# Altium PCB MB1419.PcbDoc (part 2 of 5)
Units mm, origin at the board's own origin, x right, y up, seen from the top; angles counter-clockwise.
Board outline 31 x 41 mm, 8 copper layers (Top Layer, Signal Layer 1, Signal Layer 2, Signal Layer 3, Signal Layer 4, Signal Layer 5, Signal Layer 6, Bottom Layer), stack 1.536 mm thick; 212 components, 125 nets, 637 pads, 2405 vias.
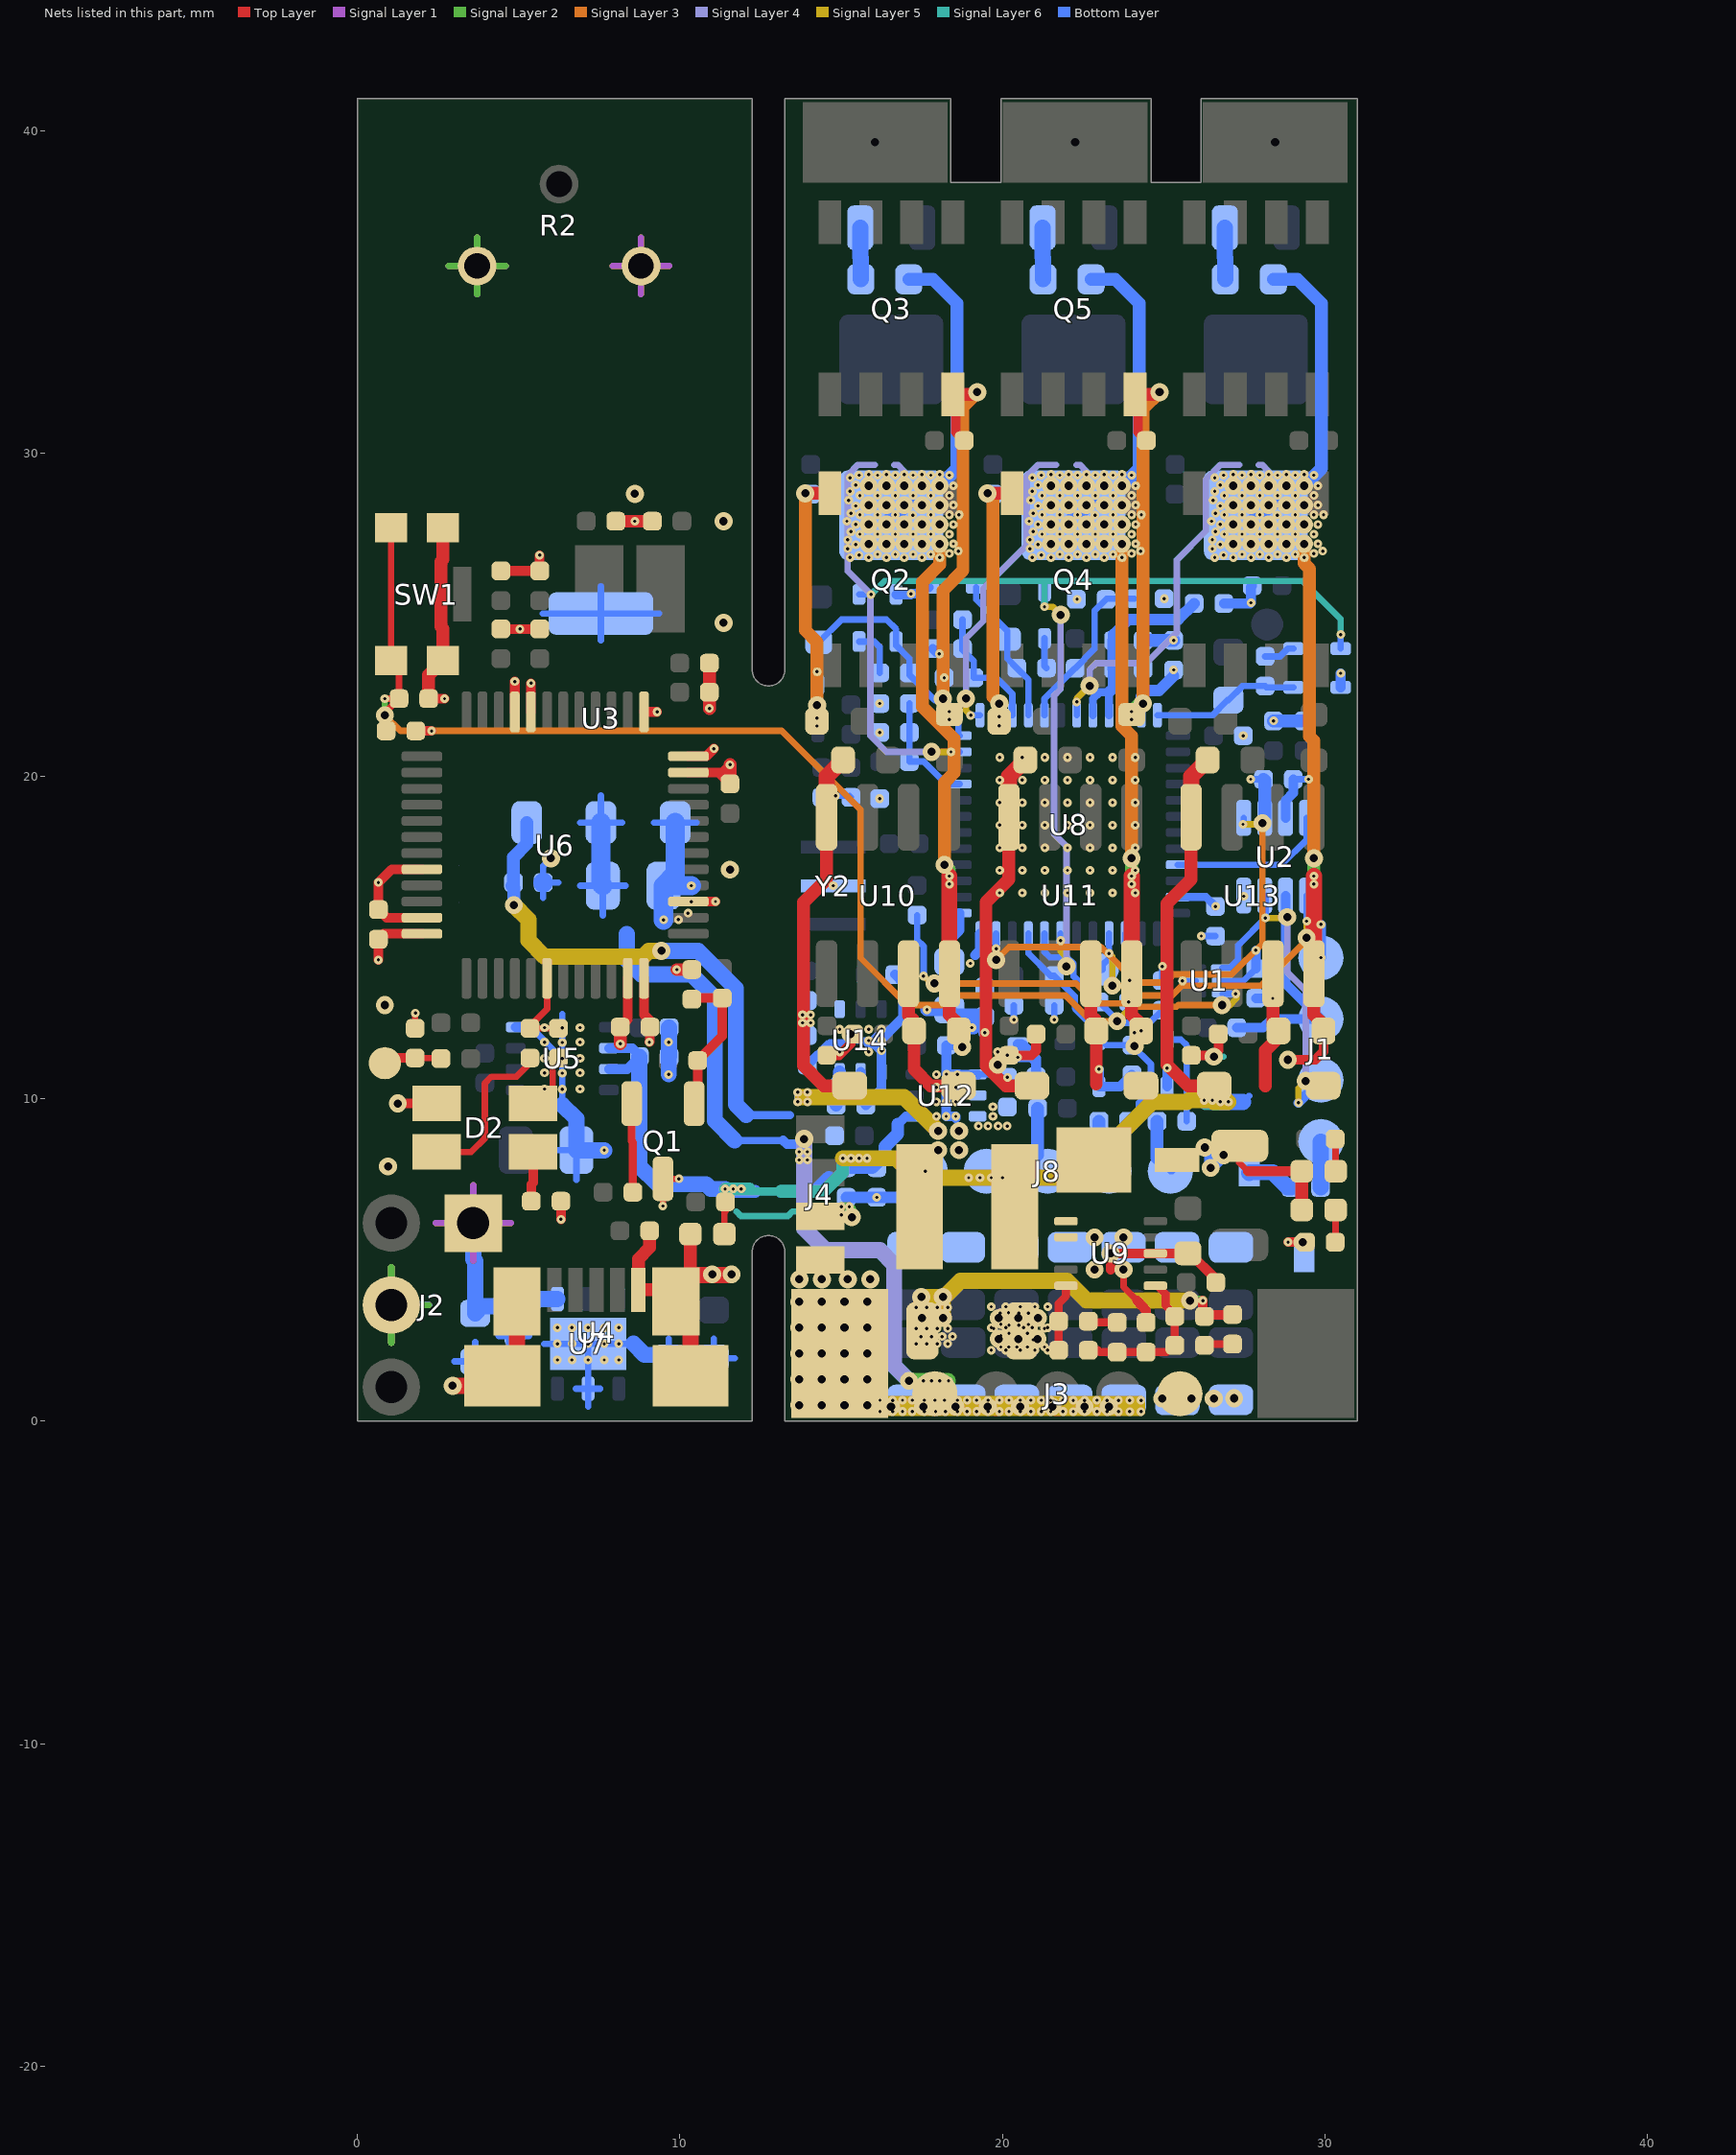
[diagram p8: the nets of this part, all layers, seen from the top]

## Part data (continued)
R64 R65 R66: library part RES, "RES SMD 22K OHM 1% 1/10W 0402", Manufacturer="Panasonic Electronic Components", Manufacturer PN=ERJ-2RKF2202X, Package Size="0402 (1005 Metric)", Rated Power="0.1W, 1/10W", Temperature Coefficient=100ppm/C, Tolerance=1%
R68: library part RES, "RES SMD 169K OHM 1% 1/16W 0402", Manufacturer=Yageo, Manufacturer PN=RC0402FR-07169KL, Package Size="0402 (1005 Metric)", Rated Power="0.063W, 1/16W", Temperature Coefficient=100ppm/C, Tolerance=1%
R74 R75 R77: library part RES, "RES SMD 1.8K OHM 1% 1/16W 0402", Manufacturer=Yageo, Manufacturer PN=RC0402FR-071K8L, Package Size="0402 (1005 Metric)", Rated Power="0.063W, 1/16W", Temperature Coefficient=100ppm/C, Tolerance=1%
R76: library part RES, "RES SMD 18K OHM 1% 1/16W 0402", Manufacturer=Yageo, Manufacturer PN=RC0402FR-0718KL, Package Size="0402 (1005 Metric)", Rated Power="0.063W, 1/16W", Temperature Coefficient=100ppm/C, Tolerance=1%
RT1: library part NTC, "NTC THERMISTOR 10K OHM 1% 0402", Manufacturer="TDK Corporation", Manufacturer PN=NTCG103JF103FT1, Package Size="0402 (1005 Metric)"
SW1: library part PUSHBUTTON-SPST-2, "SWITCH TACTILE SPST-NO 0.05A 32V", Manufacturer=C&K, Manufacturer PN=KMR211GLFS, Package Size="4.60mm x 2.80mm"
TP1 TP2 TP3: library part TESTPOINT, "TEST POINT 1MM  SMD PADSTASCK"
U1: library part AS11P2TLR, "IC ANLG SWITCH SGL SPDT 6QFN", Manufacturer=STMicroelectronics, Package Size=6-UFDFN
U2: library part TCAN330, "IC TXRX CAN 3.3V SOT-23", Manufacturer="Texas Instruments", Package Size=SOT-23-8, Supply Voltage="3 V ~ 3.6 V"
U3: library part LD1117SxxxTR_0, "IC REG LINEAR 5V 800MA SOT223", Manufacturer=STMicroelectronics, Package Size="TO-261-4, TO-261AA"
U4: library part USB_MICRO, "CONN RCPT 5POS MICRO USB R/A", Manufacturer="Molex, LLC", Manufacturer PN=0473460001
U5: "IC PWR SWITCH 1.2A HISIDE 8-DFN", Manufacturer=STMicroelectronics, Package Size="8-VDFN Exposed Pad", Supply Voltage="Not Required"
U6: "IC MCU 32BIT 128KB FLASH 48LQFP", Manufacturer=STMicroelectronics, Package Size=48-LQFP, Supply Voltage="2 V ~ 3.6 V"
U7: "IC REG LINEAR 3.3V 500MA 6DFN", Manufacturer=STMicroelectronics, Package Size="6-VDFN Exposed Pad"
U8: library part STM32_LQFP64_6
U9: "IC REG BUCK ADJ 3A 10VDFPN", Manufacturer=STMicroelectronics, Package Size="10-VFDFN Exposed Pad"
U10 U11 U13: library part L6387E, "IC DRIVER HI/LO SIDE HV 8-SOIC", Manufacturer=STMicroelectronics, Package Size="8-SOIC (0.154\", 3.90mm Width)", Supply Voltage="17V (Max)"
U12 U14: library part LDFPxR, "IC REG LINEAR POS ADJ 1A 6DFN", Manufacturer=STMicroelectronics, Package Size="6-VDFN Exposed Pad"
Y1: library part crystal, "CRYSTAL 8.0000MHZ 8PF SMD", Frequency Stability=150ppm, Frequency Tolerance=50ppm, Manufacturer="NDK America, Inc.", Package Size="0.126\" L x 0.098\" W (3.20mm x 2.50mm)"
Y2: library part resonator, "CER RES 8.0000MHZ 33PF SMD", Frequency Stability=0.13%, Frequency Tolerance=0.1%, Manufacturer="Murata Electronics North America", Manufacturer PN=CSTNE8M00GH5C000R0, Package Size="0.126\" L x 0.051\" W (3.20mm x 1.30mm)"

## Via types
v1: diameter 0.27, hole 0.1, Top Layer to Signal Layer 1, 715 vias
v2: diameter 0.27, hole 0.1, Signal Layer 6 to Bottom Layer, 503 vias
v3: diameter 0.27, hole 0.1, Signal Layer 1 to Signal Layer 2, 497 vias
v4: diameter 0.27, hole 0.1, Signal Layer 5 to Signal Layer 6, 309 vias
v5: diameter 0.559, hole 0.254, Top Layer to Bottom Layer, 214 vias
v6: diameter 0.559, hole 0.254, Signal Layer 2 to Signal Layer 5, 155 vias
v7: diameter 0.254, hole 0.254, Top Layer to Bottom Layer, 12 vias

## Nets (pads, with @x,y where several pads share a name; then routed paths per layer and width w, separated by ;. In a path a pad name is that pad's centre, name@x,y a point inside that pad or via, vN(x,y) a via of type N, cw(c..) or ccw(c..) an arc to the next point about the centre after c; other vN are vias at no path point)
5V_ESC: C9.1 C57.1 C63.1 C70.1 D1.C J8.4 R42.2 U5.6 U5.7 U12.1 U14.5 U14.6 | length 37.7
  Signal Layer 5 w0.5: v4(15.05,8.15) v4(15.3,8.15) v4(15.55,8.15) v4(15.8,8.15) 16.7,8.15 17.3,7.55 v2(18.95,7.55) v2(19.3,7.55) v2(19.65,7.55) v2(20,7.55) 22.3,7.55 24.65,9.9 25.713,9.9 25.763,9.95 v4(26.25,9.95) v4(26.5,9.95) 26.55,9.9 v4(26.75,9.9) v4(27,9.9)
  Signal Layer 6 w0.2: 12.146,7.2 12.2,7.146
  Signal Layer 6 w0.25: 12.2,7.146 12.225,7.121 13.129,7.121
  Signal Layer 6 w0.4: v2(11.4,7.2) v2(11.65,7.2) v2(11.9,7.2) 12.146,7.2 ; 13.129,7.121 14.458,7.121 15.05,7.713 v4(15.05,8.15) v4(15.3,8.15) v4(15.55,8.15) v4(15.8,8.15)
  Signal Layer 6 w0.5: v4(26.25,9.95) 26.3,9.9 26.45,9.9 v4(26.5,9.95) 26.55,9.9 v4(26.75,9.9) v4(27,9.9)
  Bottom Layer w0.2: C9.1@8.74,11.3 C9.1@8.74,11.35 ; 27.45,9.9 27.631,10.081 D1.C@27.65,10.081
  Bottom Layer w0.25: 12.323,7.127 12.477,7.127 12.483,7.121 12.917,7.121 12.923,7.127 13.15,7.127
  Bottom Layer w0.3: U5.7@7.795,10.915 8.365,10.915 8.74,11.29 C9.1@8.74,11.3 ; U5.6@7.795,11.565 8.525,11.565 C9.1@8.74,11.35 ; U14.6@14.95,10.6 15.103,10.447 15.386,10.447 15.6,10.661 U14.5@15.6,10.825 ; 16.75,9.2 17,9.45 U12.1@17.275,9.45
  Bottom Layer w0.4: v2(11.4,7.2) 11.45,7.2 11.523,7.127 12.323,7.127 ; 13.15,7.127 14.177,7.127 14.61,7.56 ; C63.1@14.84,9.8 14.84,10.49 14.95,10.6 U14.6@14.95,10.825 ; C57.1@15.15,7.86 15.95,7.86 16.35,8.26 16.35,8.51 16.75,8.91 16.75,9.2
  Bottom Layer w0.5: C9.1@8.74,11.29 8.74,7.91 9.3,7.35 10.8,7.35 10.95,7.2 v2(11.4,7.2) ; v4(26.25,9.95) 26.7,9.95 v4(26.75,9.9) 27.45,9.9
  other v2: 15.05,8.15 15.3,8.15 15.55,8.15 15.8,8.15 26.75,9.9 26.25,9.95
  other v4: 18.95,7.55 19.3,7.55 19.65,7.55 20,7.55
+3.3V: C1.1 C2.1 C18.1 C19.2 C20.1 C24.1 C64.1 D10.C D12.C D14.C D16.C D17.C D18.C D19.C J4.3 L1.1 R29.1 R49.2 R64.2 R65.2 R66.2 R71.1 R72.1 R73.2 RT1.1 U1.2 U2.3 U8.1 U8.23 U8.35 U8.48 U14.1 | length 21.6
  Top Layer w0.2: J4.3@14.7,6.35 15,6.35 v3(15,6.4) v3(15,6.65)
  Top Layer w0.3: v3(28.85,5.55) R29.1@29.39,5.55
  Signal Layer 2 w0.2: v3(15,6.4) 15,6.45 15.15,6.6 15.2,6.6 v3(15.25,6.65) v6@15.25,6.45 ; v3(28.85,5.55) v6(29.3,5.55)
  Signal Layer 2 w0.27: v3(15,6.4) 15.075,6.325 v6(15.325,6.325) 15.325,6.575 v3(15.25,6.65) v3(15,6.65) v3@15,6.45
  Bottom Layer w0.2: v4(13.8,12.35) 13.95,12.2 C64.1@13.95,11.96 ; R71.1@24.95,13.66 v4(24.95,14.1) ; U1.2@26.82,13.65 27.47,13.65 C1.1@27.85,14.03 ; C2.1@29.01,19.9 v4(29.487,19.9)
  Bottom Layer w0.25: U8.23@24.3,21.885 24.3,22.465 ; C24.1@25.3,23.1 v4(25.3,23.29) ; U8.35@25.435,16.25 26.31,16.25 v4(26.6,15.96)
  Bottom Layer w0.3: v4(14.25,23.237) 14.27,23.217 D16.C@14.27,22.83 ; D10.C@16.7,25.63 17.143,25.63 v4(17.163,25.65) 17.35,25.65 17.55,25.85 D12.C@17.72,25.85 ; R65.2@17.84,23.95 17.94,23.85 17.98,23.85 v4(18.04,23.79) ; 18.45,15 18.665,15.215 U8.1@18.665,15.75 ; 19.15,14.45 19.3,14.6 U8.48@19.3,15.115 ; R73.2@21.04,10.68 21.04,11.13 ; v4(22.99,10.91) D18.C@22.99,10.37 23.64,10.37 R72.1@24.01,10.74 ; D17.C@25.1,10.37 v4(25.1,10.95) ; L1.1@26.86,25.35 27.677,25.35 v4(27.7,25.373) 27.7,25.86 RT1.1@27.74,25.9 ; C1.1@27.85,14.03 v4(27.85,14.6) ; U2.3@28.775,18.705 28.775,19.24 29.01,19.475 C2.1@29.01,19.9 ; D14.C@30.48,22.75 v4(30.48,23.187) ; D19.C@20.47,11.7 v4(20.47,11.28) 20.89,11.28 ; D19.C@20.47,11.7 20.89,11.28 ; D19.C@20.47,11.7 20.59,11.7 21.01,11.28 ; 20.89,11.28 21.01,11.28 ; 20.89,11.28 21.04,11.13 ; 21.01,11.28 21.04,11.25 21.04,11.13
  Bottom Layer w0.35: 24.3,22.465 24.485,22.65 24.85,22.65 C24.1@25.3,23.1
  other v1: 28.85,5.55 15,6.4 15,6.65 15.25,6.65
  other v2: 22.99,10.91 25.1,10.95 20.47,11.28 13.8,12.35 14.05,12.35 13.8,12.6 14.05,12.6 24.95,14.1 19,14.195 27.85,14.6 26.6,15.96 29.487,19.9 16.19,22.25 30.48,23.187 14.25,23.237 25.3,23.29 18.04,23.79 27.7,25.373 22.31,25.48 17.163,25.65
  other v4: 14.05,12.35 13.8,12.6 14.05,12.6 19,14.195 16.19,22.25 22.31,25.48
+3V3_ST_LINK: C3.1 C4.1 C16.1 C17.1 J2.1 Q1.3 R2.3 R10.1 R11.1 R15.1 R19.2 U6.1 U6.9 U6.24 U6.36 U6.39 U6.48 U7.4 | length 33.2
  Top Layer w0.2: v1(9.47,6.67) Q1.3@9.47,7.515 v1(9.965,7.515)
  Top Layer w0.3: v1(0.65,14.3) C3.1@0.65,14.94 0.82,15.11 U6.24@2,15.11 ; R10.1@1.81,21.4 v1(2.3,21.4) ; R19.2@4.45,26.36 R15.1@5.65,26.36 v3(5.65,26.85) ; U6.9@4.88,21.99 v1(4.88,22.93) ; v1(6.31,6.26) R11.1@6.31,6.82 ; U6.36@8.88,13.73 8.88,12.61 9.07,12.42 9.07,11.77 v1(9.05,11.75) ; U6.1@8.88,21.99 v1(9.29,21.99) ; U6.39@10.26,16.11 v1(11.1,16.11) ; U6.48@10.26,20.61 10.81,20.61 v1(11.05,20.85)
  Signal Layer 1 w0.2: 2.423,6.14 J2.1@3.59,6.14 ; 3.59,4.973 J2.1@3.59,6.14 ; 3.59,7.307 J2.1@3.59,6.14 ; 4.757,6.14 J2.1@3.59,6.14 ; 7.912,35.815 R2.3@8.79,35.815 ; 8.79,34.937 R2.3@8.79,35.815 ; 8.79,36.693 R2.3@8.79,35.815 ; 9.668,35.815 R2.3@8.79,35.815
  Signal Layer 5 w0.2: 2.423,6.14 J2.1@3.59,6.14 ; 3.59,4.973 J2.1@3.59,6.14 ; 3.59,7.307 J2.1@3.59,6.14 ; 4.757,6.14 J2.1@3.59,6.14 ; 7.912,35.815 R2.3@8.79,35.815 ; 8.79,34.937 R2.3@8.79,35.815 ; 8.79,36.693 R2.3@8.79,35.815 ; 9.668,35.815 R2.3@8.79,35.815
  Bottom Layer w0.5: J2.1@3.59,6.14 3.59,5.024 3.65,4.964 C16.1@3.65,3.345 3.865,3.56 C17.1@4.85,3.56 5.367,3.56 5.597,3.79 U7.4@6.2,3.79
  other v1: 5.65,26.85
+5V: C6.1 J3.1 U3.2 U3.4 | length 38.3
  Top Layer w0.2: J3.1@17.9,0.85 J3.1@18.05,0.85 ; J3.1@18.297,1.25 J3.1@18.323,1.25
  Signal Layer 2 w0.2: v6(17.1,1.25) 17.108,1.258 v3@17.442,1.258
  Signal Layer 2 w0.5: v6(17.1,1.25) v3(17.55,1.25) v3(17.8,1.25) v3(18.05,1.25) v3@18.297,1.25
  Signal Layer 4 w0.5: v6(13.85,8.75) 13.85,5.971 14.521,5.3 16.2,5.3 16.636,4.864 16.636,1.714 v6(17.1,1.25)
  Signal Layer 5 w0.2: v4(13.7,8.35) 13.825,8.225 v4(13.95,8.1) ; v4(13.7,8.35) 13.7,8.6 v6(13.85,8.75) ; v4(13.7,8.35) v4(13.7,8.1) v4(13.95,8.1) ; v4(13.7,8.35) v4(13.95,8.35) ; v6(13.85,8.75) 13.95,8.65 v4@13.95,8.4 ; v6(13.85,8.75) 13.85,8.5 v4@13.95,8.4 ; v4(13.95,8.1) v4(13.95,8.35) ; v4(13.95,8.35) v4@13.95,8.4
  Bottom Layer w0.2: 5.747,25.04 U3.4@7.55,25.04 ; 6.897,18.56 U3.2@7.55,18.56 ; 6.907,16.6 C6.1@7.61,16.6 ; 7.55,19.398 U3.2@7.55,18.56 ; 7.55,24.202 U3.4@7.55,25.04 ; 7.55,25.878 U3.4@7.55,25.04 ; 7.61,15.682 C6.1@7.61,16.6 ; 7.61,17.518 C6.1@7.61,16.6 ; 8.203,18.56 U3.2@7.55,18.56 ; 8.313,16.6 C6.1@7.61,16.6 ; 8.35,15.1 8.35,15.2 ; 9.353,25.04 U3.4@7.55,25.04 ; v4(13.7,8.35) v4(13.7,8.1) v4(13.95,8.1)
  Bottom Layer w0.22: 11.7,8.7 13.2,8.7
  Bottom Layer w0.3: 13.2,8.7 13.314,8.586 13.85,8.586
  Bottom Layer w0.5: 8.35,15.1 8.35,14.3 8.8,13.85 10.352,13.85 11.08,13.122 11.08,9.32 11.7,8.7
  Bottom Layer w0.6: U3.2@7.55,18.56 7.55,16.66 C6.1@7.61,16.6
  other v1: 17.55,1.25 17.8,1.25 18.05,1.25 18.325,1.25
  other v2: 13.7,8.1 13.95,8.1 13.7,8.35 13.95,8.35
  other v3: 18.325,1.25
+10V: C5.1 C42.2 C45.2 C49.1 C55.1 C56.1 C62.1 D6.A D8.A D9.A L2.2 R30.1 U3.3 U10.3 U11.3 U12.5 U12.6 U13.3 | length 48.6
  Top Layer w0.3: v3(26.21,3.74) 26.21,3.4 26.26,3.35 R30.1@26.26,3.25 26.31,3.3 27.12,3.3 C42.2@27.13,3.31
  Top Layer w0.4: U10.3@17.085,13.875 17.085,12.578 17.255,12.408 C49.1@17.255,12.1 17.255,10.918 17.773,10.4 D6.A@18.575,10.4 ; U11.3@22.735,13.875 22.735,12.578 22.905,12.408 C55.1@22.905,12.1 22.905,10.449 ; 28.15,10.4 28.15,11.5 28.555,11.905 C62.1@28.555,12.1 28.385,12.27 U13.3@28.385,13.875
  Signal Layer 2 w0.3: v6(25.81,3.74) v3(26.21,3.74)
  Signal Layer 3 w0.2: v6@18.085,3.87 18.1,3.856 v6(18.15,3.856)
  Signal Layer 5 w0.2: 14.1,10.05 v4(13.95,10.2) ; v4(13.65,10.2) v4(13.95,10.2) ; v4(13.65,10.2) v4(13.65,9.9) v4(13.95,9.9) ; v4(13.65,10.2) v4(13.95,9.9) ; v4(13.95,9.9) v4(13.95,10.2)
  Signal Layer 5 w0.5: v5(4.85,16) 5.3,15.55 5.3,14.9 5.8,14.4 8.85,14.4 9.031,14.581 v5(9.422,14.581) ; 14.1,10.05 16.95,10.05 v6(18,9) ; v6(25.81,3.74) 22.61,3.74 22,4.35 18.7,4.35 18.206,3.856 v6(18.15,3.856) ; v6(17.479,3.848) 17.811,3.516 v6@18.127,3.2 ; v6(17.479,3.848) 17.479,3.221 v6(17.5,3.2) v6@18.127,3.2 ; v6(17.479,3.848) 17.487,3.856 v6(18.15,3.856) ; v6@18.127,3.2 v6(18.15,3.2) v6(18.15,3.856)
  Bottom Layer w0.2: C5.1@4.79,16.6 4.79,16.65 C5.1@4.84,16.7 ; 12.05,9.5 12.057,9.493 ; 13.412,9.493 13.419,9.5 ; v4(13.65,9.9) 13.641,9.908 13.641,10.192 v4(13.65,10.2)
  Bottom Layer w0.25: 12.057,9.493 13.412,9.493
  Bottom Layer w0.4: v5(4.85,16) 4.85,16.54 4.79,16.6 4.84,16.65 C5.1@4.84,16.7 4.84,17.49 5.25,17.9 U3.3@5.25,18.56
  Bottom Layer w0.5: v5(9.422,14.581) 10.569,14.581 11.73,13.42 11.73,9.82 12.05,9.5
  other v1: 17.325,2.4 17.65,2.4 17.975,2.4 18.3,2.4 17.475,2.625 17.8,2.625 18.125,2.625 18.45,2.625 17.325,2.875 17.65,2.875 17.975,2.875 18.3,2.875 17.325,3.525 17.65,3.525 17.975,3.525 18.3,3.525 26.21,3.74
  other v2: 19.25,9.15 19.55,9.15 19.86,9.15 20.142,9.15 19.7,9.45 19.7,9.75 13.65,9.9 13.95,9.9 13.65,10.2 13.95,10.2
  other v3: 17.325,2.4 17.65,2.4 17.975,2.4 18.3,2.4 17.475,2.625 17.8,2.625 18.125,2.625 18.45,2.625 17.325,2.875 17.65,2.875 17.975,2.875 18.3,2.875 17.325,3.525 17.65,3.525 17.975,3.525 18.3,3.525
  other v4: 19.25,9.15 19.55,9.15 19.86,9.15 20.142,9.15 19.7,9.45 19.7,9.75
  other v6: 18,8.4 18.65,8.4 18.65,9
A+/H1: C67.1 D17.A R71.2 R74.2 U8.44 | length 9.5
  Bottom Layer w0.2: U8.44@21.3,15.115 21.3,14.55 21.47,14.38 22,14.38 22.2,14.18 22.2,13.79 23.64,12.35 24.56,12.35 R71.2@24.95,12.74 25.1,12.59 D17.A@25.1,11.83 25.527,11.83 25.71,11.647 R74.2@25.71,9.3
B+/H2: C68.1 D18.A R72.2 R75.2 U8.45 | length 8.2
  Bottom Layer w0.2: U8.45@20.8,15.115 20.8,14.5 21.49,13.81 C68.1@21.6,13.81 22.24,13.17 22.24,12.8 22.99,12.05 D18.A@22.99,11.83 23.05,11.83 23.22,11.66 R72.2@24.01,11.66 24.6,11.07 24.6,10.25 24.22,9.87 24.22,9.61 R75.2@23.91,9.3
BEMF1: D10.A R57.1 R61.2 U8.12 | length 7.1
  Bottom Layer w0.2: R61.2@14.3,24.145 15.005,24.85 16.4,24.85 16.7,24.55 D10.A@16.7,24.17 16.7,24.05 17.11,23.64 17.11,23.138 17.898,22.35 18.2,22.35 18.63,21.92 18.63,21.25 U8.12@18.665,21.25
BEMF2: D12.A R58.1 R62.2 U8.16 | length 4.6
  Bottom Layer w0.2: D12.A@19.18,25.85 19.18,25.47 20.15,24.5 R62.2@20.15,24.245 20.15,23.64 R58.1@20.44,23.35 20.8,22.99 U8.16@20.8,21.885
BEMF3: D14.A R59.1 R63.2 U8.24 | length 4.6
  Bottom Layer w0.2: U8.24@24.8,21.885 26.5,21.885 26.97,22.355 R63.2@27,22.355 27.435,22.79 R59.1@28.14,22.79 28.18,22.75 D14.A@29.02,22.75
BUTTON: C8.1 R10.2 SW1.3 SW1.4 U8.39 | length 40
  Top Layer w0.2: v3(0.85,22.4) C8.1@1.29,22.4 ; R10.2@0.89,21.4 0.89,22 C8.1@1.29,22.4 ; SW1.3@1.045,27.695 SW1.4@1.045,23.584 1.29,23.34 C8.1@1.29,22.4
  Signal Layer 2 w0.2: v6(0.85,21.884) v3(0.85,22.4)
  Signal Layer 3 w0.2: v6(0.85,21.884) 1.334,21.4 13.15,21.4 15.6,18.95 15.6,14.35 17.05,12.9 18.35,12.9 18.65,13.2 21.95,13.2 22.75,12.4 v6(23.55,12.4)
  Signal Layer 5 w0.2: v6(23.55,12.4) 23.941,12.792 v4(23.941,13.662)
  Bottom Layer w0.2: U8.39@23.8,15.115 23.8,14.403 23.941,14.262 v4(23.941,13.662)
  other v1: 0.85,22.4
  other v2: 23.941,13.662
CAN_RX: U2.4 U8.33 | length 5
  Bottom Layer w0.2: U8.33@25.435,17.25 28.65,17.25 29.425,18.025 U2.4@29.425,18.705
CAN_SHDN: TP2.1 U2.5 U8.40 | length 10.5
  Signal Layer 3 w0.2: v6(23.4,13.5) 23.75,13.5 24.05,13.2 25.25,13.2 25.55,13.5 28,13.5 29.425,14.925 v6(29.425,14.987)
  Signal Layer 5 w0.2: v4(23.3,14.5) 23.4,14.4 v6(23.4,13.5) ; v6(29.425,14.987) v4(29.425,15.503)
  Bottom Layer w0.2: TP2.1@23.1,14 23.1,14.15 23.3,14.35 v4(23.3,14.5) U8.40@23.3,15.115 ; v4(29.425,15.503) U2.5@29.425,16.295
  other v2: 23.3,14.5 29.425,15.503
CAN_TERM: R26.2 U1.3 | length 12.8
  Signal Layer 3 w0.2: v6(17.89,13.571) 22.279,13.571 22.9,12.95 23.8,12.95 23.85,12.9 23.855,12.9 23.905,12.85 25.395,12.85 25.445,12.9 v6(26.8,12.9) v6@26.82,12.9
  Signal Layer 5 w0.2: v4(17.55,13.8) 17.561,13.8 17.79,13.571 v6(17.89,13.571) ; v6(26.8,12.9) 27.05,12.9 27.25,13.1 v4@27.25,13.25
  Bottom Layer w0.2: R26.2@17.35,15.69 17.35,14.923 17.55,14.723 v4(17.55,13.8) ; U1.3@26.82,13.25 v2@27.25,13.25
  other v2: 27.225,13.25 17.55,13.8
  other v4: 27.225,13.25
CAN_TX: U2.1 U8.47 | length 14.7
  Signal Layer 3 w0.2: v6(19.8,14.3) 20.2,14.7 23.049,14.7 24.149,13.6 25.05,13.6 25.3,13.85 27.1,13.85 28.057,14.807 v6(28.057,18.539)
  Signal Layer 5 w0.2: v6(19.8,14.3) v4(19.8,14.65) ; v4(27.455,18.505) 28.023,18.505 v6(28.057,18.539)
  Bottom Layer w0.2: v4(19.8,14.65) U8.47@19.8,15.115 ; v4(27.455,18.505) 27.475,18.525 U2.1@27.475,18.705
  other v2: 19.8,14.65 27.455,18.505
CURR_FDBK1_OPAMP+: R64.1 R67.1 R80.2 U8.9 | length 3.6
  Bottom Layer w0.2: R64.1@17.11,22.25 R80.2@17.11,21.35 R67.1@17.11,20.45 17.55,20.45 18.25,19.75 U8.9@18.665,19.75
CURR_FDBK1_OPAMP-: JP1.1 U8.11 | length 12.3
  Signal Layer 4 w0.2: JP1.1@16.035,29.65 15.515,29.65 15.2,29.335 15.2,26.35 15.9,25.65 15.9,21.25 16.4,20.75 v6(17.8,20.75)
  Signal Layer 5 w0.2: v6(17.8,20.75) v4(18.4,20.75)
  Bottom Layer w0.2: v4(18.4,20.75) U8.11@18.665,20.75
  other v2: 18.4,20.75
CURR_FDBK2_OPAMP+: R65.1 R69.1 R81.2 U8.15 | length 4
  Bottom Layer w0.2: R69.1@18.76,24.85 R65.1@18.76,23.95 18.76,23.907 19.11,23.557 R81.2@19.11,23.05 19.795,23.05 20.3,22.545 U8.15@20.3,21.885
CURR_FDBK2_OPAMP-: JP2.1 U8.13 | length 9.6
  Signal Layer 4 w0.2: v6(18.865,22.401) 18.865,24.265 19.4,24.8 19.4,25.805 20.75,27.155 20.75,29.3 21.1,29.65 JP2.1@21.66,29.65
  Signal Layer 5 w0.2: v6(18.865,22.401) 18.865,22.035 v4(19.015,21.885)
  Bottom Layer w0.2: v4(19.015,21.885) U8.13@19.3,21.885
  other v2: 19.015,21.885
CURR_FDBK3_OPAMP+: R66.1 R70.1 R82.2 U8.17 | length 5.3
  Bottom Layer w0.2: U8.17@21.3,21.885 21.3,22.4 22.24,23.34 R70.1@22.25,23.34 22.85,23.94 22.85,25.12 R66.1@23.21,25.48 23.23,25.5 R82.2@24.09,25.5
CURR_FDBK3_OPAMP-: JP3.1 U8.19 | length 11.1
  Signal Layer 4 w0.2: v6(22.7,22.8) 22.7,23.3 22.9,23.5 24.45,23.5 25.4,24.45 25.4,26.7 26.3,27.6 26.3,29.2 26.75,29.65 JP3.1@27.34,29.65
  Signal Layer 5 w0.2: v4(22.3,22.3) 22.3,22.4 v6(22.7,22.8)
  Bottom Layer w0.2: U8.19@22.3,21.885 v4(22.3,22.3)
  other v2: 22.3,22.3
D: J1.2 U1.1 U2.7 | length 10.7
  Signal Layer 4 w0.2: v6(28.825,15.625) 28.825,13.925 29.4,13.35 v6(29.4,10.55)
  Signal Layer 5 w0.2: v4(28.15,15.6) 28.8,15.6 v6(28.825,15.625) ; v4(29.172,9.872) 29.172,10.322 v6(29.4,10.55)
  Bottom Layer w0.2: U1.1@26.805,14.05 27.04,14.05 27.3,14.31 27.3,14.75 v4(28.15,15.6) 28.15,16.295 U2.7@28.125,16.295
  Bottom Layer w0.3: v4(29.172,9.872) J1.2@29.87,10.57
  other v2: 29.172,9.872 28.15,15.6
GND: C1.2 C2.2 C3.2 C4.2 C5.2 C6.2 C7.2 C8.2 C9.2 C10.1 C11.1 C12.1 C13.2 C14.2 C15.2 C16.2 C17.2 C18.2 C19.1 C20.2 C21.2 C22.2 C23.2 C24.2 C25.2 C26.2 C27.1 C28.1 C29.1 C30.1 C31.1 C32.1 C33.1 C34.1 C35.1 C36.1 C37.1 C38.1 C39.1 C40.1 C41.2 C44.2 C45.1 C47.2 C48.2 C49.2 C51.2 C53.2 C54.2 C55.2 C56.2 C57.2 C59.2 C60.2 C61.2 C62.2 C63.2 C64.2 C65.2 C66.2 C67.2 C68.2 C69.2 C70.2 D2.C1 D3.C D4.C D5.C D7.A D20.A J1.4 J2.3 J3.5 J4.4 J6.1 J8.5 JP1.2 JP2.2 JP3.2 R2.1 R6.1 R7.1 R13.2 R14.2 R16.2 R17.2 R22.2 R32.2 R33.1 R46.2 R53.2 R54.2 R55.2 R56.2 R60.2 R76.2 R80.1 R81.1 R82.1 SW1.1 SW1.2 U1.5 U2.2 U2.8 U3.1 U4.5 U4.6 U4.7 U4.8 U4.9 U5.4 U5.9 U6.8 U6.20 U6.23 U6.35 U6.47 U7.2 U7.7 U8.49 U9.8 U9.11 U10.4 U11.4 U12.4 U12.7 U13.4 U14.4 U14.7 Y2.2 | length 257.3
  Top Layer w0.2: C12.1@1.79,12.18 1.79,12.64 v3(1.8,12.65) ; v5(23.75,4.7) 23.75,4.159 24.169,3.74 ; 26.21,11.34 26.25,11.3 v5(26.55,11.3) 26.69,11.44 v5@26.69,11.483 ; 27.333,8.017 27.6,7.75
  Top Layer w0.3: v5(1.25,9.85) D2.C1@2.45,9.85 ; U6.23@2,15.61 0.9,15.61 C3.2@0.65,15.86 v3(0.65,16.7) 1.06,17.11 U6.20@2,17.11 ; C8.2@2.21,22.4 v3(2.7,22.4) ; R22.2@4.45,24.56 v3(5.04,24.56) C13.2@5.65,24.56 ; U6.8@5.38,21.99 v3(5.38,22.88) ; C4.2@8.15,12.22 8.38,12.45 U6.35@8.38,13.73 ; U6.47@10.26,20.11 11.2,20.11 ; R13.2@11.55,19.76 11.2,20.11 ; v3(11.55,20.35) 11.31,20.11 11.2,20.11 ; C47.2@14.55,11.34 14.93,11.34 15.29,11.7 v5(15.29,12) C48.2@15.39,12 ; C49.2@18.645,12.1 18.645,11.705 v5(18.75,11.6) ; C53.2@20.2,11.34 20.897,11.34 21.04,11.483 C54.2@21.04,12 ; 23.35,4.7 v5(23.35,5.2) U9.8@24.735,5.2 25.103,5.2 25.108,5.205 C41.2@25.75,5.205 25.805,5.205 26.61,4.4 R32.2@26.61,4.3 ; 24.169,3.74 24.45,3.43 R33.1@24.45,3.06 ; C60.2@25.85,11.34 26.21,11.34 26.547,11.34 26.69,11.483 C61.2@26.69,12 ; 27.6,7.75 D4.C@29.275,7.75 ; v5(28.841,11.205) 29.692,11.205 29.945,11.458 C62.2@29.945,12.1
  Top Layer w0.4: C8.2@2.21,22.4 2.21,23.14 SW1.2@2.655,23.584 2.655,24.568 2.59,24.633 2.59,26.648 2.655,26.712 SW1.1@2.655,27.695 ; C10.1@8.01,27.9 v3(8.6,27.9) C11.1@9.14,27.9 ; v3(8.15,11.7) C4.2@8.15,12.22 ; R7.1@9.06,5.9 9.06,5.383 8.71,5.033 U4.5@8.71,4.074 9.505,4.074 U4.7@9.873,3.706 U4.7@9.873,4.073 ; v3(9.9,14) R6.1@10.37,14 ; D3.C@10.325,5.8 10.325,4.575 9.873,4.123 U4.7@9.873,4.073 ; U4.7@10.335,4.535 U4.7@9.873,4.073 ; v3(10.91,22.1) R17.2@10.91,23.5 ; R13.2@11.55,19.76 v3(11.55,20.35) ; U10.4@18.355,13.575 U10.4@18.355,13.875 18.35,13.87 18.35,12.6 18.645,12.305 C49.2@18.645,12.1 ; U11.4@24.005,13.575 U11.4@24.005,13.875 24,13.87 24,12.6 24.295,12.305 v3(24.295,12.1) ; D5.C@29.275,6.55 D4.C@29.275,7.75 ; U13.4@29.655,13.575 U13.4@29.655,13.875 29.65,13.87 29.65,12.6 29.945,12.305 C62.2@29.945,12.1
  Top Layer w0.5: v5(2.95,1.1) 4.181,1.1 U4.8@4.491,1.41 4.947,1.866 U4.6@4.947,3.706 ; U4.7@9.873,3.706 10.329,3.25 U4.9@10.329,1.41 ; U4.7@10.335,4.535 10.985,4.535 v5(11,4.55) 11.015,4.535 v5@11.515,4.535 ; v3(18.35,16.9) v3(18.35,16.65) 18.35,13.88 U10.4@18.355,13.875 ; v3(24,16.9) v3(24,16.65) 24,13.88 U11.4@24.005,13.875 ; v3(29.65,16.9) v3(29.65,16.65) 29.65,13.88 U13.4@29.655,13.875
  Signal Layer 1 w0.27: v1(19.925,3.35) 19.94,3.365 v3(20.185,3.365) ; v1(19.947,2.302) v3(20.197,2.302) ; v1(19.947,2.652) 20.127,2.652 v1(20.2,2.725)
  Signal Layer 2 w0.2: 1.05,2.433 J2.3@1.05,3.6 ; 1.05,4.767 J2.3@1.05,3.6 ; 2.217,3.6 J2.3@1.05,3.6 ; 2.832,35.815 R2.1@3.71,35.815 ; 3.71,34.937 R2.1@3.71,35.815 ; 3.71,36.693 R2.1@3.71,35.815 ; 4.588,35.815 R2.1@3.71,35.815 ; v6(19.85,11.05) v3(20.15,11.35) ; v6@20.697,3.352 20.747,3.352 20.897,3.202 v6(21.1,3.202) ; v6(24.09,11.626) 24.1,11.636 24.1,11.65 24.295,11.845 v3(24.295,12.1)
  Signal Layer 2 w0.4: v6(18.2,17.25) 18.35,17.1 v3(18.35,16.9) v3(18.35,16.65) ; v3(24,16.65) v3(24,16.9) v6(24,17.45) ; v3(29.65,16.65) v3(29.65,16.9) v6(29.65,17.45)
  Signal Layer 3 w0.2: 1.05,2.433 J2.3@1.05,3.6 1.05,4.767 ; 2.832,35.815 R2.1@3.71,35.815 ; 3.71,34.937 R2.1@3.71,35.815 ; 3.71,36.693 R2.1@3.71,35.815 ; 4.588,35.815 R2.1@3.71,35.815
  Signal Layer 3 w0.4: v2(18.05,27.2) 18.05,26.55 17.521,26.021 17.521,22.139 18.5,21.16 18.5,20.1 18.2,19.8 v6(18.2,17.25) ; v2(23.7,27.2) 23.7,21.55 24,21.25 v6(24,17.45) ; v2(29.35,27.2) 29.35,26.594 29.516,26.428 29.516,21.234 29.65,21.1 v6(29.65,17.45)
  Signal Layer 4 w0.2: 1.05,2.433 J2.3@1.05,3.6 ; 1.05,4.767 J2.3@1.05,3.6 ; 2.217,3.6 J2.3@1.05,3.6 ; 2.832,35.815 R2.1@3.71,35.815 ; 3.71,34.937 R2.1@3.71,35.815 ; 3.71,36.693 R2.1@3.71,35.815 ; 4.588,35.815 R2.1@3.71,35.815 ; JP1.2@16.635,29.65 16.75,29.65 16.95,29.45 v2(16.95,29) ; JP2.2@22.285,29.65 22.4,29.65 22.6,29.45 v2(22.6,29) ; JP3.2@27.935,29.65 28.05,29.65 28.25,29.45 v2(28.25,29)
  Signal Layer 5 w0.2: v6(16.542,0.45) 16.592,0.4 v2(16.592,0.298) ; v6(19.85,11.05) v4(19.85,11.45) ; v6(24.09,11.626) v4(24.09,12.05)
  Signal Layer 5 w0.27: v4(16.9,0.3) 16.9,0.45 ; v4(17.2,0.3) 17.2,0.45 ; 16.342,0.65 v6(16.542,0.45) 16.9,0.45 ; 16.342,0.65 v4(16.2,0.65) v4(16.2,0.3) 16.202,0.298 v2(16.592,0.298) v4(22.192,0.298) v4(23.592,0.298) v4(23.942,0.298) v4(24.292,0.298) v4(24.292,0.648) ; 16.342,0.65 v4(16.9,0.65) ; 16.9,0.45 17.2,0.45 ; 16.9,0.45 v4(16.9,0.65) ; v4(16.9,0.65) v4(17.2,0.65) ; 17.2,0.45 v6(17.542,0.45) v6(18.542,0.45) v6(19.542,0.45) v6(20.542,0.45) v6(21.542,0.45) v6(22.542,0.45) v6(23.292,0.45) 24.094,0.45 v4(24.292,0.648) ; 17.2,0.45 v4(17.2,0.65) ; v4(17.2,0.65) v4(17.9,0.65) v4(18.2,0.65) v4(18.9,0.65) v4(19.2,0.65) v4(19.9,0.65) v4(20.2,0.65) v4(20.875,0.65) v4(21.2,0.65) v4(21.875,0.65) v4(22.925,0.65) 24.289,0.65 v4(24.292,0.648)
  Signal Layer 6 w0.2: 1.05,2.433 J2.3@1.05,3.6 ; 1.05,4.767 J2.3@1.05,3.6 ; 2.217,3.6 J2.3@1.05,3.6 ; 2.832,35.815 R2.1@3.71,35.815 ; 3.71,34.937 R2.1@3.71,35.815 ; 3.71,36.693 R2.1@3.71,35.815 ; 4.588,35.815 R2.1@3.71,35.815 ; 11.75,6.5 11.893,6.357 13.34,6.357 13.483,6.5 13.75,6.5 ; v5(26.55,11.3) 26.85,11.3
  Bottom Layer w0.2: 1.05,2.433 J2.3@1.05,3.6 ; 1.05,4.767 J2.3@1.05,3.6 ; 2.217,3.6 J2.3@1.05,3.6 ; 3.007,1.855 C16.2@3.65,1.855 ; 3.65,1.257 C16.2@3.65,1.855 ; 3.65,2.453 C16.2@3.65,1.855 ; 4.382,2.64 C17.2@4.85,2.64 5.318,2.64 ; 5.375,12.215 v2(6.35,11.24) ; 5.76,16.232 C5.2@5.76,16.7 ; 5.79,2.4 v2(6.2,2.4) v2(6.65,2.4) v2(7.15,2.4) ; C5.2@5.91,16.6 5.86,16.6 C5.2@5.76,16.7 ; v5(6,17.45) 5.76,17.21 C5.2@5.76,16.7 ; 6.087,8.4 C7.2@6.79,8.4 6.79,7.482 ; 6.228,16.7 C5.2@5.76,16.7 ; 6.35,9.862 v2(6.35,10.29) v2(6.35,10.79) v2(6.35,11.24) ; 6.35,12.618 v2(6.35,12.19) v2(6.35,11.74) v2(6.35,11.24) ; 6.772,1.01 U7.2@7.15,1.01 ; 7.15,0.457 U7.2@7.15,1.01 ; 7.528,1.01 U7.2@7.15,1.01 ; 8.51,2.4 v2(8.1,2.4) v2(7.65,2.4) v2(7.15,2.4) ; 9.007,1.955 C14.2@9.65,1.955 ; 9.197,18.56 U3.1@9.85,18.56 10.503,18.56 ; 9.65,1.357 C14.2@9.65,1.955 ; 9.65,2.553 C14.2@9.65,1.955 ; v2(9.65,10.75) v2@9.66,10.74 ; C9.2@9.65,11.26 9.65,11.29 C9.2@9.66,11.3 v2@9.66,10.74 ; v2(9.65,11.75) v2@9.66,11.76 ; 9.66,10.614 v2@9.66,10.74 ; 10.293,1.955 C14.2@9.65,1.955 ; 10.407,1.955 C15.2@11.05,1.955 ; 11.05,2.553 C15.2@11.05,1.955 ; 11.693,1.955 C15.2@11.05,1.955 ; C23.2@14.4,19.34 14.45,19.39 v2(14.823,19.39) 15.25,19.39 R76.2@15.3,19.34 ; v5(15.29,12) 15.49,11.8 U14.7@15.6,11.8 15.7,11.8 ; 16,11.8 v2@15.95,11.8 ; R54.2@16.45,28.085 R54.2@16.55,28.085 16.85,28.085 R54.2@17.248,28.483 ; v2(17.6,7.75) J8.5@17.65,7.7 ; U12.7@18.25,10.1 v2(18.25,10.35) 18.26,10.36 v2(18.26,10.76) ; U12.4@19.225,10.75 19.732,10.75 19.822,10.66 v2(20.15,10.66) ; v2(20.35,12.45) C69.2@20.35,12.89 ; v2(21.6,12.45) C68.2@21.6,12.89 ; R55.2@22.1,28.085 R55.2@22.2,28.085 22.5,28.085 22.695,28.28 R55.2@22.898,28.483 ; v2@25.55,13.65 U1.5@25.98,13.65 ; v2(26.16,15.04) C20.2@26.6,15.04 ; v2(27.69,19.9) C2.2@28.09,19.9 ; R56.2@27.75,28.085 R56.2@27.85,28.085 28.15,28.085 R56.2@28.548,28.483 ; U7.2@7.15,1.01 v2(7.15,1.9) v2(7.15,2.4) ; 15.7,11.8 15.8,11.7 15.85,11.7 v2@15.95,11.8 ; 15.7,11.8 v2(15.85,11.8) v2@15.95,11.8
  Bottom Layer w0.22: C34.1@17.12,0.66 ccw(c17.482,0.66) 17.482,0.298 18.418,0.298 ccw(c18.418,0.66) C30.1@18.78,0.66
  Bottom Layer w0.3: U5.4@4.905,12.215 5.375,12.215 ; C64.2@13.95,11.04 14.25,11.34 14.289,11.34 14.649,11.7 15.19,11.7 15.29,11.8 v5(15.29,12) ; C63.2@15.76,9.8 16.25,10.29 U14.4@16.25,10.825 v2(16.25,11.482) 16.032,11.7 v2@15.85,11.7 ; 16,11.8 16.1,11.9 16.3,11.9 16.4,12 16.918,12.518 16.918,13.592 R53.2@16.66,13.85 ; U12.7@18.25,10.1 v2(18.25,9.9) v2(18.25,9.45) v2(18.55,9.45) v2@18.55,9.4 ; v5(18.75,11.6) 18.7,11.65 R46.2@18.26,11.65 v2(18.26,10.76) 18.647,10.76 18.657,10.75 U12.4@19.225,10.75 ; C1.2@27.85,13.11 v2(28.377,13.11) ; v2(29.87,14.37) v2(29.87,15.4)
  Bottom Layer w0.35: C57.2@15.15,6.94 v2(16.1,6.94) 16.89,6.94 J8.5@17.65,7.7
  Bottom Layer w0.4: C51.2@17.095,35.4 17.842,35.4 18.587,34.655 18.587,29.537 v2(18.05,29) ; v2(17.655,12.755) C19.1@18.35,12.755 18.505,12.6 19.39,12.6 C18.2@19.45,12.54 ; v2(19.05,12.2) 19.11,12.2 C18.2@19.45,12.54 ; v2(19.45,12.05) C18.2@19.45,12.54 ; C59.2@22.745,35.4 23.492,35.4 24.237,34.655 24.237,29.537 v2(23.7,29) ; C25.2@24.36,23.33 C26.2@24.36,24.2 24.37,24.21 v2(25.3,24.21) ; v5(26.265,8.485) 26.45,8.3 v5(26.45,7.85) v5(26.85,8.25) ; C2.2@28.09,19.9 28.125,19.865 U2.2@28.125,18.705 ; C65.2@28.395,35.4 29.142,35.4 29.887,34.655 29.887,29.537 v2(29.35,29) ; v2(28.4,21.71) R60.2@29.35,21.71
  Bottom Layer w0.5: C16.2@3.65,1.855 4.795,1.855 4.85,1.91 C17.2@4.85,2.64 ; 6.35,9.813 6.79,9.373 C7.2@6.79,8.4 v2(7.65,8.4) ; 8.56,2.4 8.905,2.055 9.55,2.055 C14.2@9.65,1.955 ; v2(9.65,10.75) C9.2@9.65,11.26 ; C9.2@9.66,11.3 9.66,11.76 R14.2@9.66,12.2
  Bottom Layer w0.6: C5.2@5.75,16.69 C5.2@5.76,16.7 ; v2(9.49,15.54) C6.2@9.49,16.6 ; C14.2@9.65,1.955 9.75,2.055 10.95,2.055 C15.2@11.05,1.955 11.05,1.229 ; U3.1@9.85,18.56 9.85,16.96 C6.2@9.49,16.6 ; v2(10.35,16.6) C6.2@9.49,16.6
  other v1: 20.197,2.302 20.447,2.302 20.775,2.3 20.95,2.525 20.5,2.625 20.775,2.725 20.2,2.975 20.5,2.975 19.947,3.002 20.8,3 20.185,3.365 20.5,3.35 20.8,3.35 20.15,11.35 8.15,11.7 24.295,12.1 1.8,12.65 9.9,14 18.35,16.65 24,16.65 29.65,16.65 0.65,16.7 18.35,16.9 24,16.9 29.65,16.9 11.55,20.35 10.91,22.1 2.7,22.4 5.38,22.88 5.04,24.56 8.6,27.9
  other v2: 21.492,0.298 22.192,0.298 22.542,0.298 23.242,0.298 23.592,0.298 23.942,0.298 24.292,0.298 16.9,0.3 17.2,0.3 17.575,0.3 17.925,0.3 18.225,0.3 18.6,0.3 18.9,0.3 19.2,0.3 19.55,0.3 19.9,0.3 20.2,0.3 20.55,0.3 20.875,0.3 21.2,0.3 21.875,0.3 22.925,0.3 16.592,0.648 16.9,0.65 17.2,0.65 17.575,0.65 17.9,0.65 18.2,0.65 18.6,0.65 18.9,0.65 19.2,0.65 19.55,0.65 19.9,0.65 20.2,0.65 20.55,0.65 20.875,0.65 21.2,0.65 21.492,0.648 21.875,0.65 22.192,0.648 22.542,0.648 22.925,0.65 23.242,0.648 23.592,0.648 23.942,0.648 24.292,0.648 6.2,1.9 6.65,1.9 7.65,1.9 8.1,1.9 6.2,2.9 6.65,2.9 7.15,2.9 7.65,2.9 8.1,2.9 17.95,9.45 17.95,9.9 18.55,9.9 5.8,10.3 6.9,10.3 17.95,10.35 18.55,10.35 17.95,10.75 18.6,10.75 5.8,10.8 6.9,10.8 5.8,11.25 6.9,11.25 14.95,11.45 15.85,11.45 5.8,11.75 6.9,11.75 16.25,11.8 14.95,12.15 15.85,12.15 16.25,12.15 5.8,12.2 6.9,12.2 23.91,13 25.575,13.65 9.95,15.55 10.25,15.75 10.35,16.1 27.475,16.275 19.911,16.377 20.611,16.377 21.311,16.377 22.011,16.377 22.711,16.377 23.411,16.377 24.111,16.377 14.75,16.6 19.911,17.077 20.611,17.077 21.311,17.077 22.011,17.077 22.711,17.077 23.411,17.077 24.111,17.077 19.911,17.777 20.611,17.777 21.311,17.777 22.011,17.777 22.711,17.777 23.411,17.777 24.111,17.777 19.911,18.477 20.611,18.477 21.311,18.477 22.011,18.477 22.711,18.477 23.411,18.477 24.111,18.477 19.911,19.177 20.611,19.177 21.311,19.177 22.011,19.177 22.711,19.177 23.411,19.177 24.111,19.177 16.19,19.3 19.911,19.877 20.611,19.877 21.311,19.877 22.011,19.877 22.711,19.877 23.411,19.877 24.111,19.877 19.911,20.577 20.611,20.577 21.311,20.577 22.011,20.577 22.711,20.577 23.411,20.577 24.111,20.577 27.46,21.25 16.19,21.35 18.19,23.05 25.01,25.5 15.275,26.775 15.85,26.775 16.4,26.775 16.95,26.775 17.5,26.775 18.05,26.775 20.925,26.775 21.5,26.775 22.05,26.775 22.6,26.775 23.15,26.775 23.7,26.775 26.575,26.775 27.15,26.775 27.7,26.775 28.25,26.775 28.8,26.775 29.35,26.775 15.55,26.85 21.2,26.85 26.85,26.85 16.125,26.875 16.675,26.875 17.225,26.875 17.775,26.875 21.775,26.875 22.325,26.875 22.875,26.875 23.425,26.875 27.425,26.875 27.975,26.875 28.525,26.875 29.075,26.875 18.35,26.9 24,26.9 29.65,26.9 18.625,26.975 24.275,26.975 29.925,26.975 15.2,27.05 20.85,27.05 26.5,27.05 15.45,27.175 21.1,27.175 26.75,27.175 15.85,27.2 16.4,27.2 16.95,27.2 17.5,27.2 18.475,27.2 21.5,27.2 22.05,27.2 22.6,27.2 23.15,27.2 24.125,27.2 27.15,27.2 27.7,27.2 28.25,27.2 28.8,27.2 29.775,27.2 15.2,27.325 20.85,27.325 26.5,27.325 15.575,27.5 16.125,27.5 16.675,27.5 17.225,27.5 17.775,27.5 18.35,27.5 21.225,27.5 21.775,27.5 22.325,27.5 22.875,27.5 23.425,27.5 24,27.5 26.875,27.5 27.425,27.5 27.975,27.5 28.525,27.5 29.075,27.5 29.65,27.5 15.3,27.575 20.95,27.575 26.6,27.575 15.45,27.8 15.85,27.8 16.4,27.8 16.95,27.8 17.5,27.8 18.05,27.8 18.475,27.8 21.1,27.8 21.5,27.8 22.05,27.8 22.6,27.8 23.15,27.8 23.7,27.8 24.125,27.8 26.75,27.8 27.15,27.8 27.7,27.8 28.25,27.8 28.8,27.8 29.35,27.8 29.775,27.8 15.175,27.9 20.825,27.9 26.475,27.9 15.575,28.1 16.125,28.1 16.675,28.1 17.216,28.09 17.775,28.1 18.35,28.1 18.65,28.1 21.225,28.1 21.775,28.1 22.325,28.1 22.866,28.09 23.425,28.1 24,28.1 24.3,28.1 26.875,28.1 27.425,28.1 27.975,28.1 28.516,28.09 29.075,28.1 29.65,28.1 29.95,28.1 15.3,28.15 20.95,28.15 26.6,28.15 15.45,28.375 21.1,28.375 26.75,28.375 15.85,28.4 16.4,28.4 16.95,28.4 17.5,28.4 18.05,28.4 18.475,28.4 21.5,28.4 22.05,28.4 22.6,28.4 23.15,28.4 23.7,28.4 24.125,28.4 27.15,28.4 27.7,28.4 28.25,28.4 28.8,28.4 29.35,28.4 29.775,28.4 15.225,28.55 20.875,28.55 26.525,28.55 15.575,28.7 16.125,28.7 16.675,28.7 17.225,28.7 17.775,28.7 18.35,28.7 21.225,28.7 21.775,28.7 22.325,28.7 22.875,28.7 23.425,28.7 24,28.7 26.875,28.7 27.425,28.7 27.975,28.7 28.525,28.7 29.075,28.7 29.65,28.7 15.275,28.825 20.925,28.825 26.575,28.825 15.85,29 16.4,29 17.5,29 18.475,29 21.5,29 22.05,29 23.15,29 24.125,29 27.15,29 27.7,29 28.8,29 29.775,29 15.45,29.025 21.1,29.025 26.75,29.025 15.275,29.25 20.925,29.25 26.575,29.25 15.55,29.325 16.125,29.325 16.675,29.325 17.225,29.325 17.775,29.325 18.35,29.325 21.2,29.325 21.775,29.325 22.325,29.325 22.875,29.325 23.425,29.325 24,29.325 26.85,29.325 27.425,29.325 27.975,29.325 28.525,29.325 29.075,29.325 29.65,29.325 15.85,29.35 16.4,29.35 16.95,29.35 17.5,29.35 18.05,29.35 21.5,29.35 22.05,29.35 22.6,29.35 23.15,29.35 23.7,29.35 27.15,29.35 27.7,29.35 28.25,29.35 28.8,29.35 29.35,29.35
  other v3: 20.775,2.3 21.3,2.3 20.2,2.725 20.775,2.725 19.725,2.875 21.3,2.875 20.2,2.975 20.8,3 20.8,3.35
  other v4: 17.925,0.3 18.225,0.3 18.9,0.3 19.2,0.3 19.9,0.3 20.2,0.3 20.875,0.3 21.2,0.3 21.875,0.3 22.925,0.3 22.192,0.648 23.592,0.648 23.942,0.648 19.65,2.2 20.1,2.2 20.55,2.2 21,2.2 21.4,2.2 19.65,2.9 20.1,2.9 20.65,2.9 20.925,2.9 21.4,2.9 19.65,3.55 20.1,3.55 20.55,3.55 21,3.55 21.4,3.55 15.275,26.775 15.85,26.775 16.4,26.775 16.95,26.775 17.5,26.775 18.05,26.775 20.925,26.775 21.5,26.775 22.05,26.775 22.6,26.775 23.15,26.775 23.7,26.775 26.575,26.775 27.15,26.775 27.7,26.775 28.25,26.775 28.8,26.775 29.35,26.775 15.55,26.85 21.2,26.85 26.85,26.85 16.125,26.875 16.675,26.875 17.225,26.875 17.775,26.875 21.775,26.875 22.325,26.875 22.875,26.875 23.425,26.875 27.425,26.875 27.975,26.875 28.525,26.875 29.075,26.875 18.35,26.9 24,26.9 29.65,26.9 18.625,26.975 24.275,26.975 29.925,26.975 15.2,27.05 20.85,27.05 26.5,27.05 15.45,27.175 21.1,27.175 26.75,27.175 18.475,27.2 24.125,27.2 29.775,27.2 15.2,27.325 20.85,27.325 26.5,27.325 15.575,27.5 16.125,27.5 16.675,27.5 17.225,27.5 17.775,27.5 18.35,27.5 21.225,27.5 21.775,27.5 22.325,27.5 22.875,27.5 23.425,27.5 24,27.5 26.875,27.5 27.425,27.5 27.975,27.5 28.525,27.5 29.075,27.5 29.65,27.5 15.3,27.575 20.95,27.575 26.6,27.575 15.45,27.8 18.475,27.8 21.1,27.8 24.125,27.8 26.75,27.8 29.775,27.8 15.175,27.9 20.825,27.9 26.475,27.9 15.575,28.1 16.125,28.1 16.675,28.1 17.216,28.09 17.775,28.1 18.35,28.1 18.65,28.1 21.225,28.1 21.775,28.1 22.325,28.1 22.866,28.09 23.425,28.1 24,28.1 24.3,28.1 26.875,28.1 27.425,28.1 27.975,28.1 28.516,28.09 29.075,28.1 29.65,28.1 29.95,28.1 15.3,28.15 20.95,28.15 26.6,28.15 15.45,28.375 21.1,28.375 26.75,28.375 18.475,28.4 24.125,28.4 29.775,28.4 15.225,28.55 20.875,28.55 26.525,28.55 15.575,28.7 16.125,28.7 16.675,28.7 17.225,28.7 17.775,28.7 18.35,28.7 21.225,28.7 21.775,28.7 22.325,28.7 22.875,28.7 23.425,28.7 24,28.7 26.875,28.7 27.425,28.7 27.975,28.7 28.525,28.7 29.075,28.7 29.65,28.7 15.275,28.825 20.925,28.825 26.575,28.825 18.475,29 24.125,29 29.775,29 15.45,29.025 21.1,29.025 26.75,29.025 15.275,29.25 20.925,29.25 26.575,29.25 15.55,29.325 16.125,29.325 16.675,29.325 17.225,29.325 17.775,29.325 18.35,29.325 21.2,29.325 21.775,29.325 22.325,29.325 22.875,29.325 23.425,29.325 24,29.325 26.85,29.325 27.425,29.325 27.975,29.325 28.525,29.325 29.075,29.325 29.65,29.325 15.85,29.35 16.4,29.35 16.95,29.35 17.5,29.35 18.05,29.35 21.5,29.35 22.05,29.35 22.6,29.35 23.15,29.35 23.7,29.35 27.15,29.35 27.7,29.35 28.25,29.35 28.8,29.35 29.35,29.35
  other v5: 13.7,0.5 14.4,0.5 15.1,0.5 15.8,0.5 24.95,0.7 25.85,0.7 26.55,0.7 27.18,0.71 13.7,1.3 14.4,1.3 15.1,1.3 15.8,1.3 13.7,2.1 14.4,2.1 15.1,2.1 15.8,2.1 13.7,2.9 14.4,2.9 15.1,2.9 15.8,2.9 13.7,3.7 14.4,3.7 15.1,3.7 15.8,3.7 13.7,4.4 14.4,4.4 15.2,4.4 15.9,4.4 11.6,4.55 22.85,4.7 22.85,5.7 23.75,5.7 0.95,7.9 0.85,12.9 11.55,17.1 11.35,24.75 11.35,27.9 8.6,28.75
  other v6: 19.885,2.55 20.485,2.55 21.085,2.55 19.885,3.2 20.485,3.2 15.85,27.2 16.4,27.2 16.95,27.2 17.5,27.2 18.05,27.2 21.5,27.2 22.05,27.2 22.6,27.2 23.15,27.2 23.7,27.2 27.15,27.2 27.7,27.2 28.25,27.2 28.8,27.2 29.35,27.2 15.85,27.8 16.4,27.8 16.95,27.8 17.5,27.8 18.05,27.8 21.5,27.8 22.05,27.8 22.6,27.8 23.15,27.8 23.7,27.8 27.15,27.8 27.7,27.8 28.25,27.8 28.8,27.8 29.35,27.8 15.85,28.4 16.4,28.4 16.95,28.4 17.5,28.4 18.05,28.4 21.5,28.4 22.05,28.4 22.6,28.4 23.15,28.4 23.7,28.4 27.15,28.4 27.7,28.4 28.25,28.4 28.8,28.4 29.35,28.4 15.85,29 16.4,29 16.95,29 17.5,29 18.05,29 21.5,29 22.05,29 22.6,29 23.15,29 23.7,29 27.15,29 27.7,29 28.25,29 28.8,29 29.35,29
GPIO_BEMF: D11.C D13.C D15.C U8.43 | length 30.6
  Signal Layer 4 w0.2: v6(21.8,25) 21.8,24.494 21.798,24.491 21.798,22.688 21.595,22.485 21.595,18.205 21.979,17.821 v6(21.979,14.1)
  Signal Layer 5 w0.2: v4(21.3,25.25) 21.55,25.25 v6(21.8,25) ; v4(21.8,14.9) 21.8,14.563 21.95,14.413 21.95,14.129 v6(21.979,14.1)
  Signal Layer 6 w0.2: v2(15.92,25.63) 16.34,26.05 21.3,26.05 ; v4(21.3,25.25) 21.3,26.05 ; v2(30.48,24.387) 30.48,24.87 29.3,26.05 21.3,26.05
  Bottom Layer w0.2: D11.C@15.55,25.63 v2(15.92,25.63) ; v4(21.3,25.25) D13.C@21.3,25.73 ; v4(21.8,14.9) U8.43@21.8,15.115 ; D15.C@30.48,23.95 v2(30.48,24.387)
  other v2: 21.8,14.9 21.3,25.25
LED_STLINK: R8.1 R9.2 U6.30 | length 2.6
  Top Layer w0.2: R9.2@5.35,12.18 R9.2@5.45,12.28 ; U6.30@5.88,13.73 5.88,12.78 5.45,12.35 R9.2@5.45,12.28 ; R8.1@6.23,12.18 5.55,12.18 R9.2@5.45,12.28
MCO: C12.2 R18.1 TP1.1 | length 1.8
  Top Layer w0.2: C12.2@1.79,11.26 2.57,11.26 R18.1@2.59,11.24
  Top Layer w0.3: TP1.1@0.85,11.1 1.01,11.26 C12.2@1.79,11.26
NetC25_1: C25.1 C26.1 L1.2 U8.20 U8.21 | length 6.6
  Bottom Layer w0.25: U8.20@22.8,21.885 22.8,22.4 23,22.6 23.3,22.6 U8.21@23.3,21.885 ; C25.1@23.44,23.33 C25.1@23.441,23.329
  Bottom Layer w0.35: 23.3,22.6 23.441,22.741 C25.1@23.441,23.329 ; C26.1@23.44,24.2 23.44,24.39 23.905,24.855 25.445,24.855 L1.2@25.94,25.35
  Bottom Layer w0.4: C25.1@23.44,23.33 C26.1@23.44,24.2
NetC42_1: C42.1 R31.1 | length 0.9
  Top Layer w0.25: R31.1@26.26,2.35 26.3,2.39 C42.1@27.13,2.39
NetC43_1: C43.1 D6.C U10.8 | length 11.7
  Top Layer w0.2: D6.C@15.16,10.4 D6.C@15.26,10.4
  Top Layer w0.4: U10.8@14.545,18.725 14.545,16.795 13.835,16.085 13.835,11.015 14.45,10.4 D6.C@15.16,10.4
  Top Layer w0.5: U10.8@14.545,18.725 14.545,19.99 C43.1@15.055,20.5
NetC46_1: C46.1 R30.2 R31.2 R33.2 R36.2 U9.6 | length 4.9
  Top Layer w0.25: C46.1@22.66,2.2 22.952,2.2 23.012,2.14 R36.2@23.55,2.14 R33.2@24.45,2.14 25.08,2.14 25.29,2.35 R31.2@25.34,2.35 R30.2@25.34,3.25 25.34,3.3 25.05,3.59 25.05,3.95 24.8,4.2 U9.6@24.735,4.2
NetC46_2: C46.2 C50.2 U9.5 | length 2.1
  Top Layer w0.25: C46.2@21.74,2.2 C50.2@21.74,3.1 21.74,3.65 21.965,3.875 U9.5@21.965,4.2
NetC50_1: C50.1 R36.1 | length 0.9
  Top Layer w0.25: C50.1@22.66,3.1 22.7,3.06 R36.1@23.55,3.06
NetC51_1: C51.1 R37.2 | length 1.6
  Bottom Layer w0.5: R37.2@15.59,37 15.59,36.083 15.605,36.068 C51.1@15.605,35.4
NetC52_1: C52.1 D8.C U11.8 | length 11.7
  Top Layer w0.2: D8.C@20.81,10.4 D8.C@20.91,10.4
  Top Layer w0.4: U11.8@20.195,18.725 20.195,16.795 19.485,16.085 19.485,11.015 20.1,10.4 D8.C@20.81,10.4
  Top Layer w0.5: U11.8@20.195,18.725 20.195,19.99 C52.1@20.705,20.5
NetC58_1: C58.1 D9.C U13.8 | length 11.7
  Top Layer w0.2: D9.C@26.46,10.4 D9.C@26.56,10.4
  Top Layer w0.4: U13.8@25.845,18.725 25.845,16.795 25.1,16.05 25.1,11.05 25.75,10.4 D9.C@26.46,10.4
  Top Layer w0.5: U13.8@25.845,18.725 25.845,19.99 C58.1@26.355,20.5
NetC59_1: C59.1 R44.2 | length 1.6
  Bottom Layer w0.5: R44.2@21.24,37 21.24,36.083 21.255,36.068 C59.1@21.255,35.4
NetC65_1: C65.1 R51.2 | length 1.6
  Bottom Layer w0.5: R51.2@26.89,37 26.89,36.083 26.905,36.068 C65.1@26.905,35.4
NetD1_A: D1.A F1.2 | length 1.5
  Bottom Layer w0.5: D1.A@27.65,7.701 27.666,7.717 28.373,7.717 28.84,7.25 F1.2@28.94,7.25
NetD2_A1: D2.A1 R8.2 | length 1.8
  Top Layer w0.2: D2.A1@5.45,9.85 5.6,9.85 6.05,10.3 6.05,11.08 R8.2@6.23,11.26
NetD2_A2: D2.A2 R11.2 | length 1.6
  Top Layer w0.3: R11.2@5.39,6.82 5.39,7.337 5.45,7.397 D2.A2@5.45,8.347
NetD2_C2: D2.C2 R9.1 | length 5.2
  Top Layer w0.2: D2.C2@2.45,8.347 3.527,8.347 3.95,8.771 3.95,10.48 4.15,10.68 4.93,10.68 5.35,11.1 R9.1@5.35,11.26
NetD3_A: D3.A R21.2 | length 1
  Top Layer w0.2: D3.A@11.375,5.8 11.375,6.477 11.41,6.512 R21.2@11.41,6.8
NetD4_A: D4.A R28.2 | length 1
  Top Layer w0.2: R28.2@30.31,8.75 30.325,8.735 D4.A@30.325,7.75
NetD5_A: D5.A R29.2 | length 1
  Top Layer w0.2: R29.2@30.31,5.55 30.325,5.565 D5.A@30.325,6.55
NetD7_C: D7.C L2.1 U9.1 U9.2
NetD11_A: D11.A R57.2 | length 1.5
  Bottom Layer w0.2: D11.A@15.55,24.17 16.03,24.17 16.19,24.01 R57.2@16.19,23.2
NetD13_A: D13.A R58.2 | length 0.9
  Bottom Layer w0.2: D13.A@21.3,24.27 21.3,23.41 R58.2@21.36,23.35
NetD15_A: D15.A R59.2 | length 1
  Bottom Layer w0.2: R59.2@28.14,23.71 28.6,23.71 28.84,23.95 D15.A@29.02,23.95
NetF1_1: F1.1 J1.1 | length 1.4
  Bottom Layer w0.5: F1.1@29.86,7.25 29.86,8.66 J1.1@29.87,8.67
NetJ1_3: J1.3 R1.2 U2.6 | length 7
  Bottom Layer w0.3: R1.2@27.26,12.2 28.073,12.2 28.343,12.47 J1.3@29.87,12.47 28.775,13.565 U2.6@28.775,16.295
NetJ8_1: J8.1 R74.1 | length 1.8
  Bottom Layer w0.2: J8.1@24.79,8.16 J8.1@25.2,7.75 25.25,7.75 J8.1@25.3,7.8
  Bottom Layer w0.4: J8.1@24.79,8.16 R74.1@24.79,9.3
NetJ8_2: J8.2 R75.1 | length 1
  Bottom Layer w0.4: J8.2@22.99,8.26 R75.1@22.99,9.3
NetJ8_3: J8.3 R77.2 | length 1.4
  Bottom Layer w0.4: J8.3@21.09,8.26 R77.2@21.09,9.7
NetQ1_1: Q1.1 R3.1 R4.2 R6.2 | length 4.6
  Top Layer w0.3: R6.2@10.37,13.08 10.41,13.12 R4.2@11.31,13.12 11.31,11.94 R3.1@10.55,11.18 10.55,9.955 Q1.1@10.44,9.845
NetQ1_2: Q1.2 R5.1 | length 2.8
  Top Layer w0.25: Q1.2@8.5,9.845 8.5,8.683 8.54,8.643 R5.1@8.54,7.1
NetQ2_4: Q2.4 R34.2 R35.1 | length 8.4
  Top Layer w0.2: R34.2@14.245,21.7 14.245,21.795 v3(14.25,21.8)
  Top Layer w0.4: v5(13.884,28.765) Q2.4@14.645,28.765
  Signal Layer 2 w0.4: v3(14.25,21.55) v3(14.25,21.8) v6(14.25,22.2)
  Signal Layer 3 w0.4: v5(13.884,28.765) 13.884,24.516 14.25,24.15 v6(14.25,22.2)
  Bottom Layer w0.2: v5(13.884,28.765) 14.025,28.765 R35.1@14.05,28.74
  other v1: 14.25,21.55 14.25,21.8
NetQ3_4: Q3.4 R38.2 R39.1 | length 13.2
  Top Layer w0.2: v3(18.35,21.75) R38.2@18.35,21.905
  Top Layer w0.3: Q3.4@18.455,31.835 18.55,31.74 18.55,30.66 R39.1@18.81,30.4
  Top Layer w0.4: Q3.4@18.455,31.835 19.085,31.835 19.15,31.9 v5(19.216,31.9)
  Signal Layer 2 w0.4: v6(18.15,22.4) 18.15,22.2 v3(18.35,22) v3(18.35,21.75)
  Signal Layer 3 w0.4: v6(18.15,22.4) 18.15,25.75 18.771,26.371 18.771,31.455 v5(19.216,31.9)
  other v1: 18.35,21.75 18.35,22
NetQ4_4: Q4.4 R40.2 R41.1 | length 8.4
  Top Layer w0.2: v3(19.895,21.555) R40.2@19.895,21.7
  Top Layer w0.4: v5(19.534,28.765) Q4.4@20.295,28.765
  Signal Layer 2 w0.2: v6@19.895,22.095 v6@19.9,22.1
  Signal Layer 2 w0.4: v3(19.895,21.555) v3(19.895,21.845) v6@19.895,22.095 ; v6@19.9,22.1 v6(19.9,22.25)
  Signal Layer 3 w0.4: v5(19.534,28.765) 19.7,28.599 19.7,22.45 v6(19.9,22.25)
  Bottom Layer w0.2: v5(19.534,28.765) 19.675,28.765 R41.1@19.7,28.74
  other v1: 19.895,21.555 19.895,21.845
NetQ5_4: Q5.4 R43.2 R45.1 | length 13.1
  Top Layer w0.2: v3(24,21.75) R43.2@24,21.905
  Top Layer w0.3: Q5.4@24.105,31.835 24.2,31.74 24.2,30.66 R45.1@24.46,30.4
  Top Layer w0.4: Q5.4@24.105,31.835 24.735,31.835 24.8,31.9 v5(24.866,31.9)
  Signal Layer 2 w0.4: v3(24,21.75) v3(24,22) 24.008,22.009 24.25,22.25 v6(24.35,22.25)
  Signal Layer 3 w0.4: v6(24.35,22.25) 24.35,31.384 v5(24.866,31.9)
  other v1: 24,21.75 24,22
